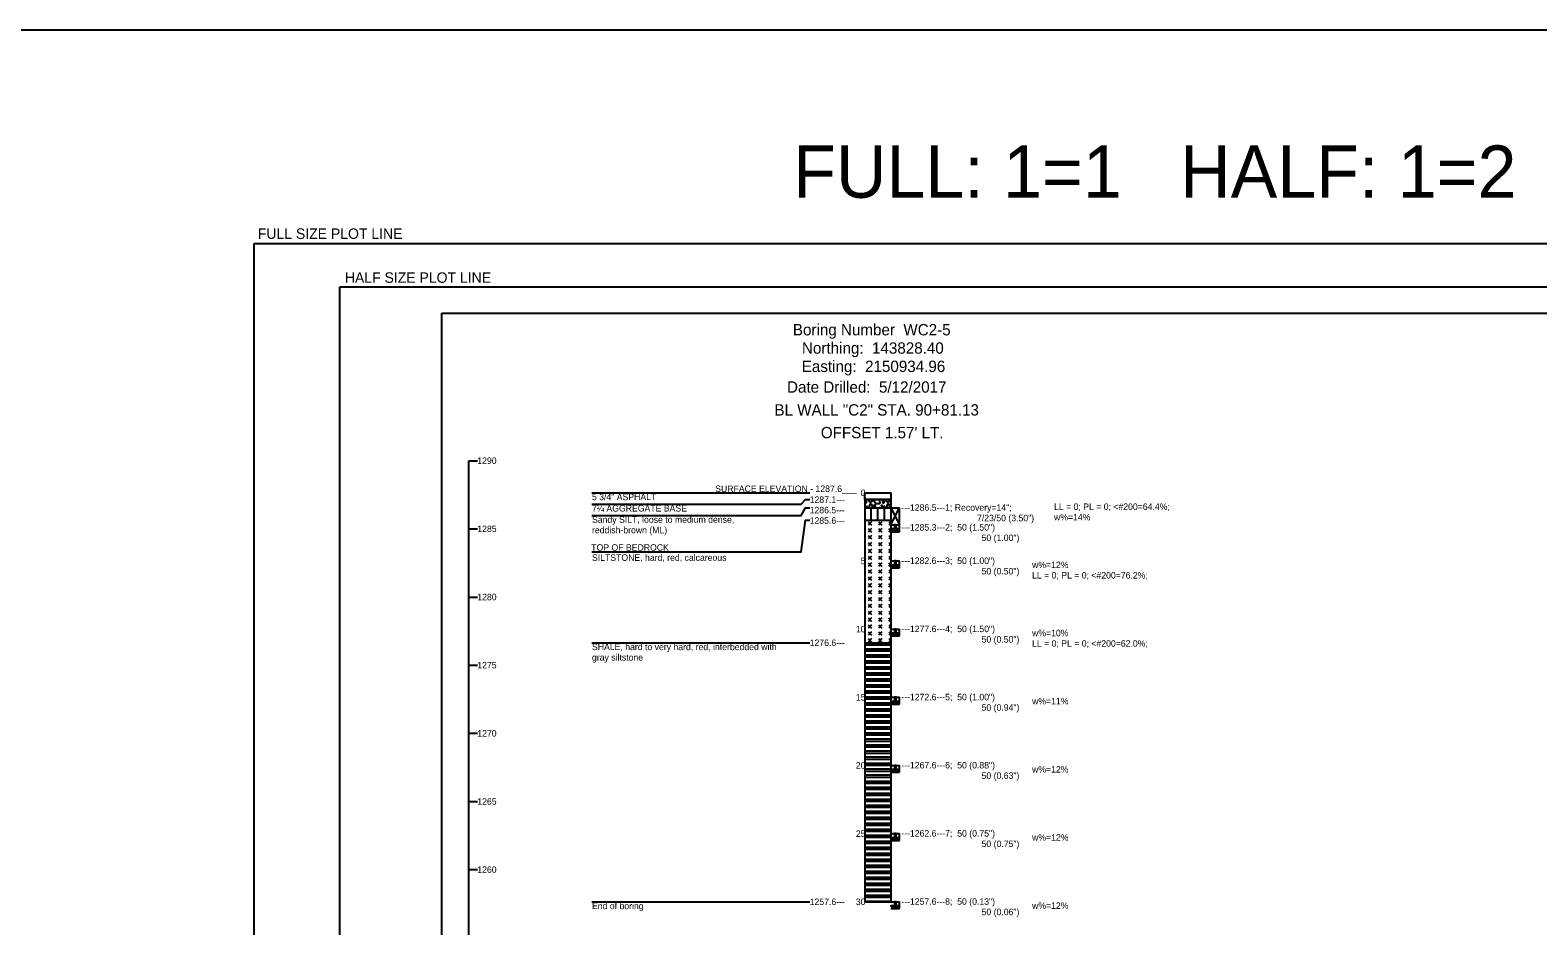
# Model space of a CAD drawing. Extents: x -2 to 138, y 24 to 58.
# Drawn here: x 85.7 to 114.52, y 40.94 to 58.05 of the extents above; entities that cross this region are included whole.
import ezdxf

# ---------------------------------------------------------------- set-up
doc = ezdxf.new("R2010")
doc.units = 0
for name, color, linetype in [('S', 7, 'Continuous'), ('SHT_Plot_Shape_Full', 7, 'Continuous'), ('SHT_Plot_Shape_Half', 7, 'Continuous'), ('SHT_Sheet_Border', 7, 'Continuous')]:
    doc.layers.add(name, color=color, linetype=linetype)

# ---------------------------------------------------------------- blocks, each defined once
blk = doc.blocks.new('POINT_DISPLAY')
blk.add_line((0, 0), (0, 0))

msp = doc.modelspace()

# ---------------------------------------------------------------- linework, layer by layer
msp.add_line((94.084, 36.804), (94.084, 49.825))
for points in [[(94.084, 49.825), (94.251, 49.825)], [(96.438, 49.212), (100.604, 49.212)], [(96.438, 48.995), (100.438, 48.995), (100.521, 49.081), (100.604, 49.081)], [(101.652, 49.119), (101.652, 41.399)], [(101.652, 49.081), (102.152, 49.081)], [(101.666, 49.051), (101.656, 49.041), (101.659, 49.031), (101.664, 49.018), (101.675, 49.016), (101.687, 49.026), (101.687, 49.04), (101.679, 49.055), (101.666, 49.051)], [(101.788, 49.081), (101.789, 49.05), (101.783, 49.042), (101.768, 49.034), (101.754, 49.035), (101.743, 49.042), (101.732, 49.05), (101.721, 49.057), (101.714, 49.071), (101.714, 49.081)], [(101.811, 48.937), (101.801, 48.951), (101.792, 48.972), (101.786, 48.987), (101.771, 48.993), (101.758, 48.998), (101.746, 48.988), (101.739, 48.957), (101.739, 48.942), (101.738, 48.925), (101.821, 48.925), (101.811, 48.937)], [(101.929, 49.081), (101.933, 49.071), (101.934, 49.06), (101.935, 49.046), (101.942, 49.035), (101.937, 49.015), (101.918, 49.004), (101.882, 49.002), (101.865, 49.007), (101.852, 49.017), (101.841, 49.036), (101.834, 49.056), (101.837, 49.081)], [(101.999, 49.051), (101.989, 49.041), (101.992, 49.031), (101.997, 49.018), (102.008, 49.016), (102.021, 49.026), (102.021, 49.04), (102.012, 49.055), (101.999, 49.051)], [(102.122, 49.081), (102.122, 49.05), (102.117, 49.042), (102.102, 49.034), (102.087, 49.035), (102.077, 49.042), (102.065, 49.05), (102.054, 49.057), (102.047, 49.071), (102.047, 49.081)], [(102.144, 48.937), (102.134, 48.951), (102.126, 48.972), (102.119, 48.987), (102.104, 48.993), (102.091, 48.998), (102.08, 48.988), (102.072, 48.957), (102.072, 48.942), (102.071, 48.925), (102.152, 48.925), (102.152, 48.927), (102.144, 48.937)], [(102.152, 49.081), (102.152, 41.399)], [(96.438, 48.778), (100.438, 48.778), (100.521, 48.925), (100.604, 48.925)], [(101.652, 48.971), (101.657, 48.963), (101.652, 48.952)], [(101.652, 48.925), (102.152, 48.925)], [(101.687, 48.956), (101.68, 48.946), (101.679, 48.935), (101.688, 48.926), (101.7, 48.928), (101.702, 48.941), (101.701, 48.951), (101.687, 48.956)], [(101.777, 48.691), (101.777, 48.925)], [(101.837, 48.978), (101.828, 48.966), (101.833, 48.955), (101.848, 48.951), (101.858, 48.958), (101.858, 48.974), (101.837, 48.978)], [(101.902, 48.691), (101.902, 48.925)], [(101.905, 48.925), (101.926, 48.929), (101.933, 48.925)], [(101.986, 48.971), (101.97, 48.976), (101.964, 48.967), (101.971, 48.956), (101.979, 48.951), (101.986, 48.952)], [(101.986, 48.971), (101.99, 48.963), (101.986, 48.952)], [(102.02, 48.956), (102.013, 48.946), (102.012, 48.935), (102.022, 48.926), (102.033, 48.928), (102.036, 48.941), (102.034, 48.951), (102.02, 48.956)], [(102.027, 48.691), (102.027, 48.925)], [(102.152, 48.925), (102.319, 48.6)], [(102.152, 48.6), (102.319, 48.925)], [(102.152, 48.925), (102.319, 48.925)], [(102.319, 48.6), (102.319, 48.925)], [(94.084, 48.523), (94.251, 48.523)], [(96.438, 48.081), (100.438, 48.081), (100.521, 48.691), (100.604, 48.691)], [(101.652, 48.691), (102.152, 48.691)], [(101.784, 48.658), (101.718, 48.592)], [(101.718, 48.658), (101.784, 48.592)], [(101.784, 48.527), (101.718, 48.461)], [(101.718, 48.527), (101.784, 48.461)], [(101.981, 48.658), (101.915, 48.592)], [(101.915, 48.658), (101.981, 48.592)], [(101.981, 48.527), (101.915, 48.461)], [(101.915, 48.527), (101.981, 48.461)], [(102.112, 48.658), (102.152, 48.617)], [(102.152, 48.633), (102.112, 48.592)], [(102.112, 48.527), (102.152, 48.486)], [(102.152, 48.502), (102.112, 48.461)], [(102.152, 48.6), (102.319, 48.6)], [(102.152, 48.6), (102.319, 48.6)], [(102.152, 48.469), (102.319, 48.469)], [(102.319, 48.469), (102.319, 48.6)], [(101.784, 48.396), (101.718, 48.33)], [(101.718, 48.396), (101.784, 48.33)], [(101.784, 48.264), (101.718, 48.199)], [(101.718, 48.264), (101.784, 48.199)], [(101.784, 48.133), (101.718, 48.067)], [(101.718, 48.133), (101.784, 48.067)], [(101.981, 48.396), (101.915, 48.33)], [(101.915, 48.396), (101.981, 48.33)], [(101.981, 48.264), (101.915, 48.199)], [(101.915, 48.264), (101.981, 48.199)], [(101.981, 48.133), (101.915, 48.067)], [(101.915, 48.133), (101.981, 48.067)], [(102.112, 48.396), (102.152, 48.355)], [(102.152, 48.371), (102.112, 48.33)], [(102.112, 48.264), (102.152, 48.224)], [(102.152, 48.239), (102.112, 48.199)], [(102.112, 48.133), (102.152, 48.092)], [(101.784, 48.002), (101.718, 47.936)], [(101.718, 48.002), (101.784, 47.936)], [(101.784, 47.871), (101.718, 47.805)], [(101.718, 47.871), (101.784, 47.805)], [(101.981, 48.002), (101.915, 47.936)], [(101.915, 48.002), (101.981, 47.936)], [(101.981, 47.871), (101.915, 47.805)], [(101.915, 47.871), (101.981, 47.805)], [(102.152, 48.108), (102.112, 48.067)], [(102.112, 48.002), (102.152, 47.961)], [(102.152, 47.977), (102.112, 47.936)], [(102.112, 47.871), (102.152, 47.83)], [(102.152, 47.846), (102.112, 47.805)], [(102.152, 47.91), (102.319, 47.91)], [(102.319, 47.779), (102.319, 47.91)], [(101.784, 47.739), (101.718, 47.674)], [(101.718, 47.739), (101.784, 47.674)], [(101.784, 47.608), (101.718, 47.542)], [(101.718, 47.608), (101.784, 47.542)], [(101.981, 47.739), (101.915, 47.674)], [(101.915, 47.739), (101.981, 47.674)], [(101.981, 47.608), (101.915, 47.542)], [(101.915, 47.608), (101.981, 47.542)], [(102.112, 47.739), (102.152, 47.699)], [(102.152, 47.714), (102.112, 47.674)], [(102.112, 47.608), (102.152, 47.567)], [(102.152, 47.583), (102.112, 47.542)], [(102.152, 47.779), (102.319, 47.779)], [(101.784, 47.477), (101.718, 47.411)], [(101.718, 47.477), (101.784, 47.411)], [(101.784, 47.346), (101.718, 47.28)], [(101.718, 47.346), (101.784, 47.28)], [(101.981, 47.477), (101.915, 47.411)], [(101.915, 47.477), (101.981, 47.411)], [(101.981, 47.346), (101.915, 47.28)], [(101.915, 47.346), (101.981, 47.28)], [(102.112, 47.477), (102.152, 47.436)], [(102.152, 47.452), (102.112, 47.411)], [(102.112, 47.346), (102.152, 47.305)], [(102.152, 47.321), (102.112, 47.28)], [(94.084, 47.221), (94.251, 47.221)], [(101.784, 47.214), (101.718, 47.149)], [(101.718, 47.214), (101.784, 47.149)], [(101.784, 47.083), (101.718, 47.018)], [(101.718, 47.083), (101.784, 47.018)], [(101.981, 47.214), (101.915, 47.149)], [(101.915, 47.214), (101.981, 47.149)], [(101.981, 47.083), (101.915, 47.018)], [(101.915, 47.083), (101.981, 47.018)], [(102.112, 47.214), (102.152, 47.174)], [(102.152, 47.189), (102.112, 47.149)], [(102.112, 47.083), (102.152, 47.042)], [(102.152, 47.058), (102.112, 47.018)], [(101.784, 46.952), (101.718, 46.886)], [(101.718, 46.952), (101.784, 46.886)], [(101.784, 46.821), (101.718, 46.755)], [(101.718, 46.821), (101.784, 46.755)], [(101.784, 46.689), (101.718, 46.624)], [(101.718, 46.689), (101.784, 46.624)], [(101.981, 46.952), (101.915, 46.886)], [(101.915, 46.952), (101.981, 46.886)], [(101.981, 46.821), (101.915, 46.755)], [(101.915, 46.821), (101.981, 46.755)], [(101.981, 46.689), (101.915, 46.624)], [(101.915, 46.689), (101.981, 46.624)], [(102.112, 46.952), (102.152, 46.911)], [(102.152, 46.927), (102.112, 46.886)], [(102.112, 46.821), (102.152, 46.78)], [(102.152, 46.796), (102.112, 46.755)], [(102.112, 46.689), (102.152, 46.649)], [(101.784, 46.558), (101.718, 46.493)], [(101.718, 46.558), (101.784, 46.493)], [(101.784, 46.427), (101.718, 46.361)], [(101.718, 46.427), (101.784, 46.361)], [(101.981, 46.558), (101.915, 46.493)], [(101.915, 46.558), (101.981, 46.493)], [(101.981, 46.427), (101.915, 46.361)], [(101.915, 46.427), (101.981, 46.361)], [(102.152, 46.665), (102.112, 46.624)], [(102.112, 46.558), (102.152, 46.518)], [(102.152, 46.533), (102.12, 46.501), (102.112, 46.493)], [(102.112, 46.427), (102.142, 46.397), (102.152, 46.386)], [(102.152, 46.402), (102.143, 46.392), (102.112, 46.361)], [(102.152, 46.607), (102.319, 46.607)], [(102.152, 46.477), (102.319, 46.477)], [(102.319, 46.477), (102.319, 46.607)], [(96.438, 46.347), (100.604, 46.347)], [(101.652, 46.347), (102.152, 46.347)], [(101.652, 46.347), (102.152, 46.347)], [(101.652, 46.308), (102.152, 46.308)], [(101.652, 46.232), (102.152, 46.232)], [(101.652, 46.193), (102.152, 46.193)], [(101.652, 46.117), (102.152, 46.117)], [(94.084, 45.919), (94.251, 45.919)], [(101.652, 46.078), (102.152, 46.078)], [(101.652, 46.003), (102.152, 46.003)], [(101.652, 45.963), (102.152, 45.963)], [(101.652, 45.888), (102.152, 45.888)], [(101.652, 45.848), (102.152, 45.848)], [(101.652, 45.773), (102.152, 45.773)], [(101.652, 45.734), (102.152, 45.734)], [(101.652, 45.658), (102.152, 45.658)], [(101.652, 45.619), (102.152, 45.619)], [(101.652, 45.543), (102.152, 45.543)], [(101.652, 45.504), (102.152, 45.504)], [(101.652, 45.428), (102.152, 45.428)], [(101.652, 45.389), (102.152, 45.389)], [(101.652, 45.314), (102.152, 45.314)], [(101.652, 45.274), (102.152, 45.274)], [(102.152, 45.305), (102.319, 45.305)], [(102.319, 45.175), (102.319, 45.305)], [(101.652, 45.199), (102.152, 45.199)], [(101.652, 45.159), (102.152, 45.159)], [(101.652, 45.084), (102.152, 45.084)], [(101.652, 45.045), (102.152, 45.045)], [(101.652, 44.969), (102.152, 44.969)], [(102.152, 45.175), (102.319, 45.175)], [(101.652, 44.93), (102.152, 44.93)], [(101.652, 44.854), (102.152, 44.854)], [(101.652, 44.815), (102.152, 44.815)], [(101.652, 44.739), (102.152, 44.739)], [(101.652, 44.7), (102.152, 44.7)], [(94.084, 44.617), (94.251, 44.617)], [(101.652, 44.625), (102.152, 44.625)], [(101.652, 44.585), (102.152, 44.585)], [(101.652, 44.51), (102.152, 44.51)], [(101.652, 44.47), (102.152, 44.47)], [(101.652, 44.395), (102.152, 44.395)], [(101.652, 44.356), (102.152, 44.356)], [(101.652, 44.28), (102.152, 44.28)], [(101.652, 44.241), (102.152, 44.241)], [(101.652, 44.165), (102.152, 44.165)], [(101.652, 44.126), (102.152, 44.126)], [(101.652, 44.05), (102.152, 44.05)], [(101.652, 44.011), (102.152, 44.011)], [(101.652, 43.936), (102.152, 43.936)], [(101.652, 43.896), (102.152, 43.896)], [(101.652, 43.821), (102.152, 43.821)], [(102.152, 44.003), (102.319, 44.003)], [(102.152, 43.873), (102.319, 43.873)], [(102.319, 43.873), (102.319, 44.003)], [(101.652, 43.781), (102.152, 43.781)], [(101.652, 43.706), (102.152, 43.706)], [(101.652, 43.667), (102.152, 43.667)], [(101.652, 43.591), (102.152, 43.591)], [(101.652, 43.552), (102.152, 43.552)], [(94.084, 43.315), (94.251, 43.315)], [(101.652, 43.476), (102.152, 43.476)], [(101.652, 43.437), (102.152, 43.437)], [(101.652, 43.361), (102.152, 43.361)], [(101.652, 43.322), (102.152, 43.322)], [(101.652, 43.247), (102.152, 43.247)], [(101.652, 43.207), (102.152, 43.207)], [(101.652, 43.132), (102.152, 43.132)], [(101.652, 43.092), (102.152, 43.092)], [(101.652, 43.017), (102.152, 43.017)], [(101.652, 42.978), (102.152, 42.978)], [(101.652, 42.902), (102.152, 42.902)], [(101.652, 42.863), (102.152, 42.863)], [(101.652, 42.787), (102.152, 42.787)], [(101.652, 42.748), (102.152, 42.748)], [(101.652, 42.672), (102.152, 42.672)], [(102.152, 42.701), (102.319, 42.701)], [(102.319, 42.571), (102.319, 42.701)], [(101.652, 42.633), (102.152, 42.633)], [(101.652, 42.558), (102.152, 42.558)], [(101.652, 42.518), (102.152, 42.518)], [(101.652, 42.443), (102.152, 42.443)], [(101.652, 42.403), (102.152, 42.403)], [(102.152, 42.571), (102.319, 42.571)], [(101.652, 42.328), (102.152, 42.328)], [(101.652, 42.289), (102.152, 42.289)], [(101.652, 42.213), (102.152, 42.213)], [(101.652, 42.174), (102.152, 42.174)], [(101.652, 42.098), (102.152, 42.098)], [(94.084, 42.013), (94.251, 42.013)], [(101.652, 42.059), (102.152, 42.059)], [(101.652, 41.984), (102.152, 41.984)], [(101.652, 41.944), (102.152, 41.944)], [(101.652, 41.869), (102.152, 41.869)], [(101.652, 41.829), (102.152, 41.829)], [(101.652, 41.754), (102.152, 41.754)], [(101.652, 41.714), (102.152, 41.714)], [(101.652, 41.639), (102.152, 41.639)], [(101.652, 41.6), (102.152, 41.6)], [(101.652, 41.524), (102.152, 41.524)], [(96.438, 41.399), (100.604, 41.399)], [(101.652, 41.485), (102.152, 41.485)], [(101.652, 41.409), (102.152, 41.409)], [(101.652, 41.399), (102.152, 41.399)], [(102.152, 41.399), (102.319, 41.399)], [(102.152, 41.269), (102.319, 41.269)], [(102.319, 41.269), (102.319, 41.399)]]:
    msp.add_lwpolyline(points)
for points in [[(101.652, 49.081), (101.652, 49.212), (102.152, 49.212), (102.152, 49.081)], [(102.219, 48.522), (102.152, 48.522), (102.236, 48.469), (102.219, 48.522)], [(102.219, 48.522), (102.252, 48.522), (102.252, 48.6), (102.219, 48.522)], [(102.219, 48.522), (102.252, 48.6), (102.219, 48.6), (102.219, 48.522)], [(102.219, 48.522), (102.236, 48.469), (102.252, 48.522), (102.219, 48.522)], [(102.236, 48.469), (102.319, 48.522), (102.252, 48.522), (102.236, 48.469)], [(102.219, 47.831), (102.252, 47.831), (102.252, 47.91), (102.219, 47.831)], [(102.219, 47.831), (102.252, 47.91), (102.219, 47.91), (102.219, 47.831)], [(102.219, 47.831), (102.152, 47.831), (102.236, 47.779), (102.219, 47.831)], [(102.219, 47.831), (102.236, 47.779), (102.252, 47.831), (102.219, 47.831)], [(102.236, 47.779), (102.319, 47.831), (102.252, 47.831), (102.236, 47.779)], [(102.219, 46.529), (102.152, 46.529), (102.236, 46.477), (102.219, 46.529)], [(102.219, 46.529), (102.252, 46.529), (102.252, 46.607), (102.219, 46.529)], [(102.219, 46.529), (102.252, 46.607), (102.219, 46.607), (102.219, 46.529)], [(102.219, 46.529), (102.236, 46.477), (102.252, 46.529), (102.219, 46.529)], [(102.236, 46.477), (102.319, 46.529), (102.252, 46.529), (102.236, 46.477)], [(102.219, 45.227), (102.252, 45.227), (102.252, 45.305), (102.219, 45.227)], [(102.219, 45.227), (102.252, 45.305), (102.219, 45.305), (102.219, 45.227)], [(102.219, 45.227), (102.152, 45.227), (102.236, 45.175), (102.219, 45.227)], [(102.219, 45.227), (102.236, 45.175), (102.252, 45.227), (102.219, 45.227)], [(102.236, 45.175), (102.319, 45.227), (102.252, 45.227), (102.236, 45.175)], [(102.219, 43.925), (102.152, 43.925), (102.236, 43.873), (102.219, 43.925)], [(102.219, 43.925), (102.252, 43.925), (102.252, 44.003), (102.219, 43.925)], [(102.219, 43.925), (102.252, 44.003), (102.219, 44.003), (102.219, 43.925)], [(102.219, 43.925), (102.236, 43.873), (102.252, 43.925), (102.219, 43.925)], [(102.236, 43.873), (102.319, 43.925), (102.252, 43.925), (102.236, 43.873)], [(102.219, 42.623), (102.252, 42.623), (102.252, 42.701), (102.219, 42.623)], [(102.219, 42.623), (102.252, 42.701), (102.219, 42.701), (102.219, 42.623)], [(102.219, 42.623), (102.152, 42.623), (102.236, 42.571), (102.219, 42.623)], [(102.219, 42.623), (102.236, 42.571), (102.252, 42.623), (102.219, 42.623)], [(102.236, 42.571), (102.319, 42.623), (102.252, 42.623), (102.236, 42.571)], [(102.219, 41.321), (102.152, 41.321), (102.236, 41.269), (102.219, 41.321)], [(102.219, 41.321), (102.252, 41.321), (102.252, 41.399), (102.219, 41.321)], [(102.219, 41.321), (102.252, 41.399), (102.219, 41.399), (102.219, 41.321)], [(102.219, 41.321), (102.236, 41.269), (102.252, 41.321), (102.219, 41.321)], [(102.236, 41.269), (102.319, 41.321), (102.252, 41.321), (102.236, 41.269)]]:
    msp.add_lwpolyline(points, close=True)
at = {"layer": 'S'}
msp.add_lwpolyline([(-2.212, 26.92), (137.529, 26.92), (137.529, 58.049), (-2.212, 58.049)], close=True, dxfattribs=at)
at = {"layer": 'SHT_Plot_Shape_Full'}
msp.add_lwpolyline([(89.979, 53.971), (125.979, 53.971), (125.979, 29.971), (89.979, 29.971)], close=True, dxfattribs=at)
at = {"layer": 'SHT_Plot_Shape_Half'}
msp.add_lwpolyline([(91.616, 53.146), (125.616, 53.146), (125.616, 31.146), (91.616, 31.146)], close=True, dxfattribs=at)
at = {"layer": 'SHT_Sheet_Border'}
msp.add_lwpolyline([(93.566, 52.646), (125.066, 52.646), (125.066, 31.646), (93.566, 31.646)], close=True, dxfattribs=at)

# ---------------------------------------------------------------- block references
at = {"xscale": 0.01, "yscale": 0.01}
for p in [(101.658, 48.842), (101.692, 48.908), (101.692, 48.742), (101.725, 48.808), (101.758, 48.875), (101.792, 48.775), (101.858, 48.908), (101.858, 48.708), (101.881, 48.845), (101.925, 48.808), (101.942, 48.733), (101.958, 48.875), (102.025, 48.808), (102.078, 48.892), (102.092, 48.742), (102.125, 48.842)]:
    msp.add_blockref('POINT_DISPLAY', p, dxfattribs=at)

# ---------------------------------------------------------------- texts
for s, height, p in [('Boring Number  WC2-5', 0.217, (100.278, 52.219)), ('Northing:  143828.40', 0.217, (100.452, 51.869)), ('Easting:  2150934.96', 0.217, (100.448, 51.519)), ('Date Drilled:  5/12/2017', 0.217, (100.166, 51.124)), ('BL WALL "C2" STA. 90+81.13', 0.217, (99.926, 50.687)), ("OFFSET 1.57' LT.", 0.217, (100.812, 50.253)), ('1290', 0.124, (94.246, 49.763)), ('SURFACE ELEVATION - 1287.6___', 0.124, (98.794, 49.227)), ('5 3/4" ASPHALT', 0.124, (96.438, 49.071)), ('1287.1---', 0.124, (100.599, 49.019)), ('0', 0.124, (101.574, 49.15)), ('---1286.5---1; Recovery=14";', 0.124, (102.35, 48.868)), ('LL = 0; PL = 0; <#200=64.4%;', 0.124, (105.27, 48.884)), ('Sandy SILT, loose to medium dense,', 0.124, (96.438, 48.638)), ('7¼ AGGREGATE BASE', 0.124, (96.438, 48.854)), ('1286.5---', 0.124, (100.599, 48.819)), ('1285.6---', 0.124, (100.599, 48.619)), ('7/23/50 (3.50")', 0.124, (103.798, 48.668)), ('w%=14%', 0.124, (105.27, 48.684)), ('1285', 0.124, (94.246, 48.461)), ('reddish-brown (ML)', 0.124, (96.438, 48.438)), ('---1285.3---2;  50 (1.50")', 0.124, (102.35, 48.49)), ('50 (1.00")', 0.124, (103.885, 48.29)), ('TOP OF BEDROCK', 0.124, (96.424, 48.105)), ('SILTSTONE, hard, red, calcareous', 0.124, (96.438, 47.912)), ('5', 0.124, (101.574, 47.848)), ('---1282.6---3;  50 (1.00")', 0.124, (102.35, 47.852)), ('w%=12%', 0.124, (104.85, 47.774)), ('50 (0.50")', 0.124, (103.885, 47.652)), ('LL = 0; PL = 0; <#200=76.2%;', 0.124, (104.85, 47.574)), ('1280', 0.124, (94.246, 47.159)), ('1276.6---', 0.124, (100.599, 46.285)), ('10', 0.124, (101.482, 46.545)), ('---1277.6---4;  50 (1.50")', 0.124, (102.35, 46.55)), ('50 (0.50")', 0.124, (103.885, 46.35)), ('w%=10%', 0.124, (104.85, 46.472)), ('SHALE, hard to very hard, red, interbedded with', 0.124, (96.438, 46.206)), ('gray siltstone', 0.124, (96.438, 46.006)), ('LL = 0; PL = 0; <#200=62.0%;', 0.124, (104.85, 46.272)), ('1275', 0.124, (94.246, 45.857)), ('15', 0.124, (101.482, 45.243)), ('---1272.6---5;  50 (1.00")', 0.124, (102.35, 45.248)), ('w%=11%', 0.124, (104.85, 45.17)), ('50 (0.94")', 0.124, (103.885, 45.048)), ('1270', 0.124, (94.246, 44.555)), ('20', 0.124, (101.482, 43.941)), ('---1267.6---6;  50 (0.88")', 0.124, (102.35, 43.946)), ('50 (0.63")', 0.124, (103.885, 43.746)), ('w%=12%', 0.124, (104.85, 43.868)), ('1265', 0.124, (94.246, 43.253)), ('25', 0.124, (101.482, 42.639)), ('---1262.6---7;  50 (0.75")', 0.124, (102.35, 42.644)), ('w%=12%', 0.124, (104.85, 42.566)), ('50 (0.75")', 0.124, (103.885, 42.444)), ('1260', 0.124, (94.246, 41.951)), ('End of boring', 0.124, (96.438, 41.258)), ('1257.6---', 0.124, (100.599, 41.337)), ('30', 0.124, (101.482, 41.337)), ('---1257.6---8;  50 (0.13")', 0.124, (102.35, 41.342)), ('50 (0.06")', 0.124, (103.885, 41.142)), ('w%=12%', 0.124, (104.85, 41.264))]:
    msp.add_text(s, height=height).set_placement(p)
at = {"layer": 'DEFPOINTS'}
for s, p in [('FULL SIZE PLOT LINE', (90.051, 54.062)), ('HALF SIZE PLOT LINE', (91.715, 53.223))]:
    msp.add_text(s, height=0.2, dxfattribs=at).set_placement(p)
at = {"layer": 'S'}
msp.add_text('FULL: 1=1   HALF: 1=2', height=1, dxfattribs=at).set_placement((100.284, 54.847))

doc.saveas('drawing.dxf')
